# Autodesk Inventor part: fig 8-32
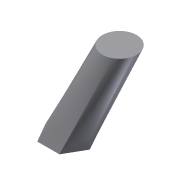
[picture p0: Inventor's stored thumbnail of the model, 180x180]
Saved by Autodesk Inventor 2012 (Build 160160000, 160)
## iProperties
Shininess: 77.0
Angle Display Precision: 2
Document Length Units: 11269
Document Angle Units: 11279
Document Time Units: 11290
Document Mass Units: 11283
Document Length Units Precision: 3
Document Angle Units Precision: 2
Created: 2001-12
Part Number: fig 8-32
Document SubType Name: Modeling
Designer: CADSoft
Density: 1 g/cm^3
Material: Default
Density: 0.0
Volumn: 0.0
Area: 0.0
PropertySet Name: Model Information
Control State: 0
Master: False
Checked Out: False
Author: CADSoft
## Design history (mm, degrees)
workplane "Work Plane3"
workplane "Work Plane4"
sketch "Sketch12"
  geometry: L1 (0, 10.598)-(9.178, -5.299); L2 (9.178, -5.299)-(-9.178, -5.299); L3 (-9.178, -5.299)-(0, 10.598); 1 further point
  constraints: 6 end point, 5 other
workplane "Work Plane5"
workplane "Work Plane6"
workplane "Work Plane7"
sketch "Sketch16"
  geometry: A1 r 72.799 centre (23.007, 110.594) between (0, 41.527) and (70, 54.995); 1 further point
  constraints: 2 point on circle, 1 centre point
loft "Loft5" dims "d57" = 0, "d58" = 90 deg, "d59" = 0, "d60" = 90 deg
body "Solid2"
sketch "Sketch1"
  geometry: L1 (19.387, 0)-(9.693, -16.79); L2 (9.693, -16.79)-(-9.693, -16.79); L3 (-9.693, -16.79)-(-19.387, 0); L4 (-19.387, 0)-(-9.693, 16.79); L5 (-9.693, 16.79)-(9.693, 16.79); L6 (9.693, 16.79)-(19.387, 0); 1 further point
  constraints: 12 end point, 11 other
sketch "Sketch2"
  geometry: C1 r 15 at (23.06, 22.535)
  constraints: 1 centre point
